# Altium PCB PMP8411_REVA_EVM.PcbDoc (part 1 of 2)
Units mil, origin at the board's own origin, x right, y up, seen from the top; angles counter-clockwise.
Board outline 4000 x 4000 mil, 6 copper layers (Top Layer, Mid-Layer 1, Mid-Layer 2, Mid-Layer 3, Mid-Layer 4, Bottom Layer), stack 118 mil thick; 118 components, 65 nets, 370 pads, 398 vias.
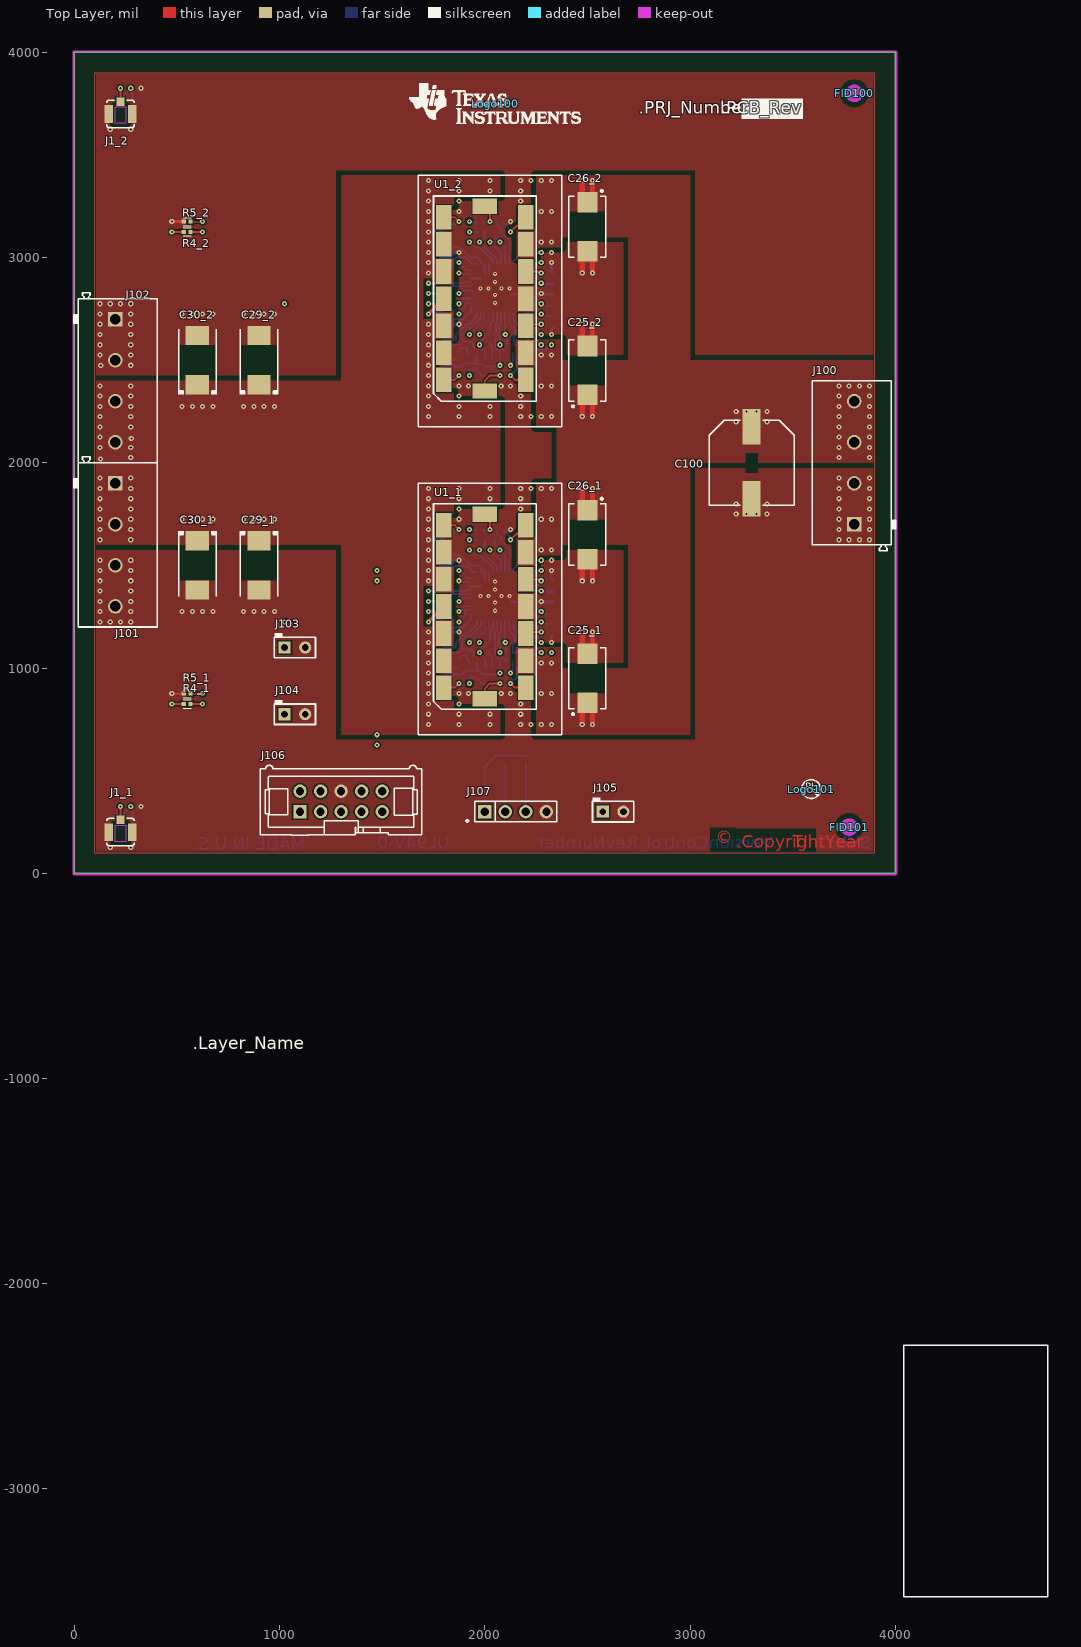
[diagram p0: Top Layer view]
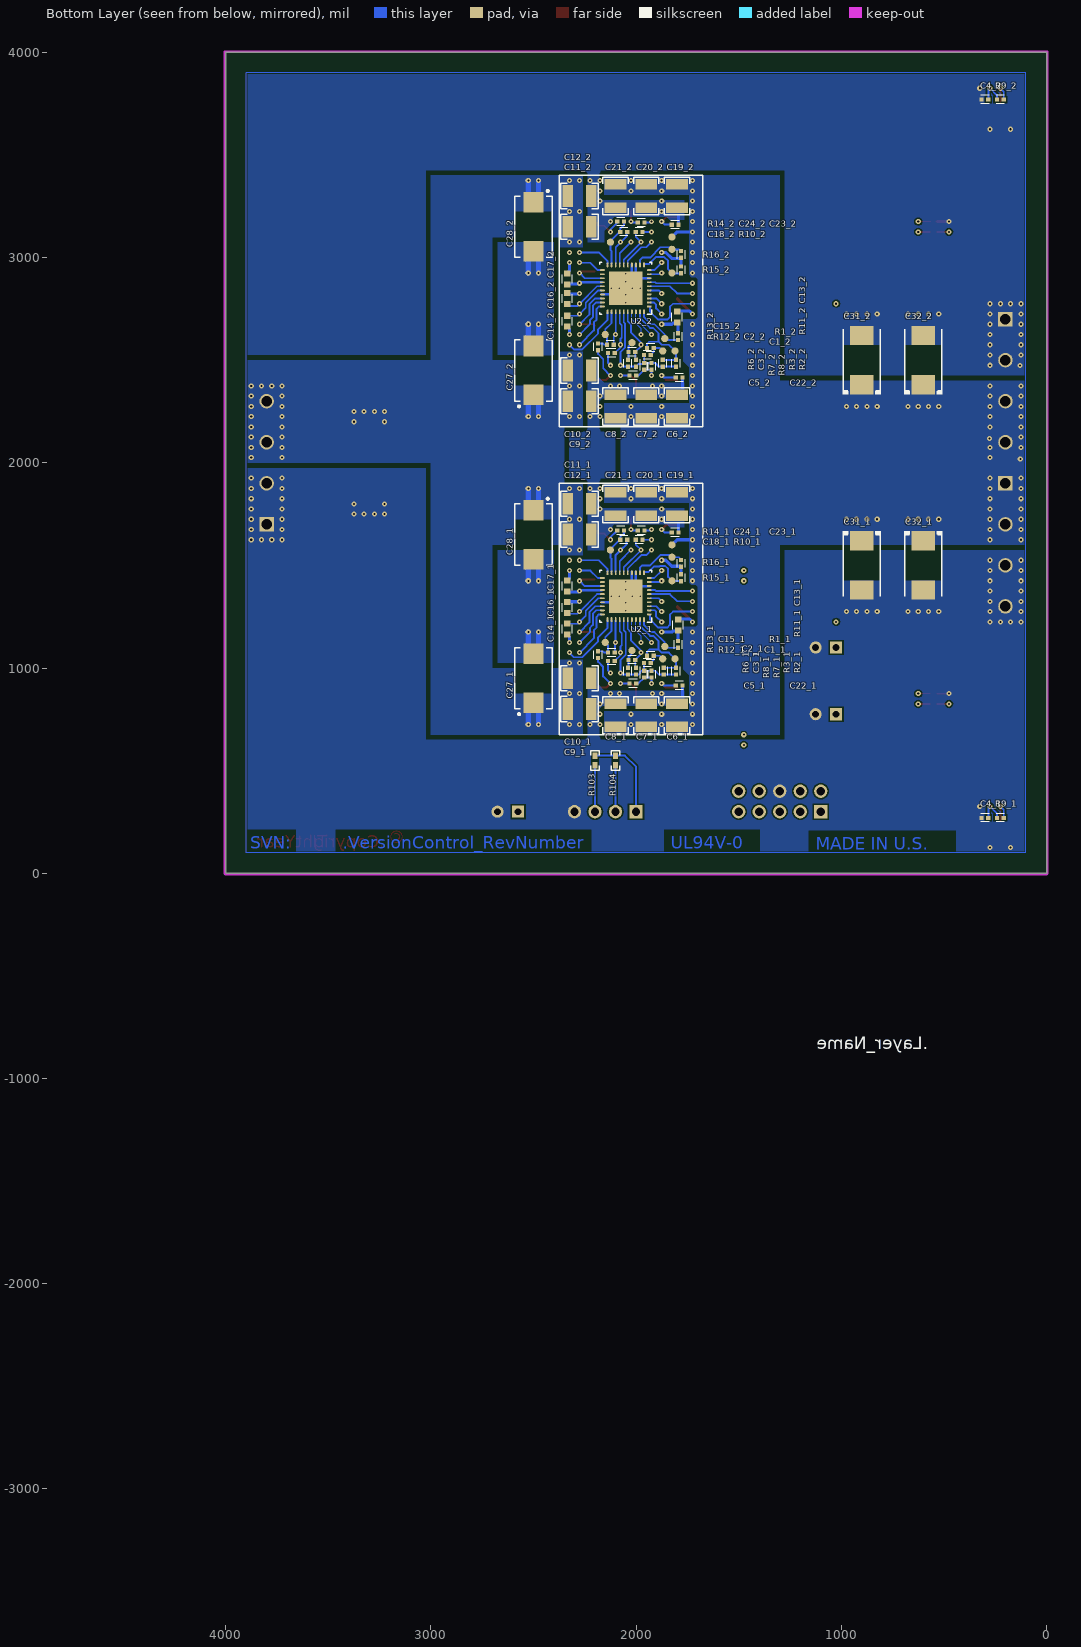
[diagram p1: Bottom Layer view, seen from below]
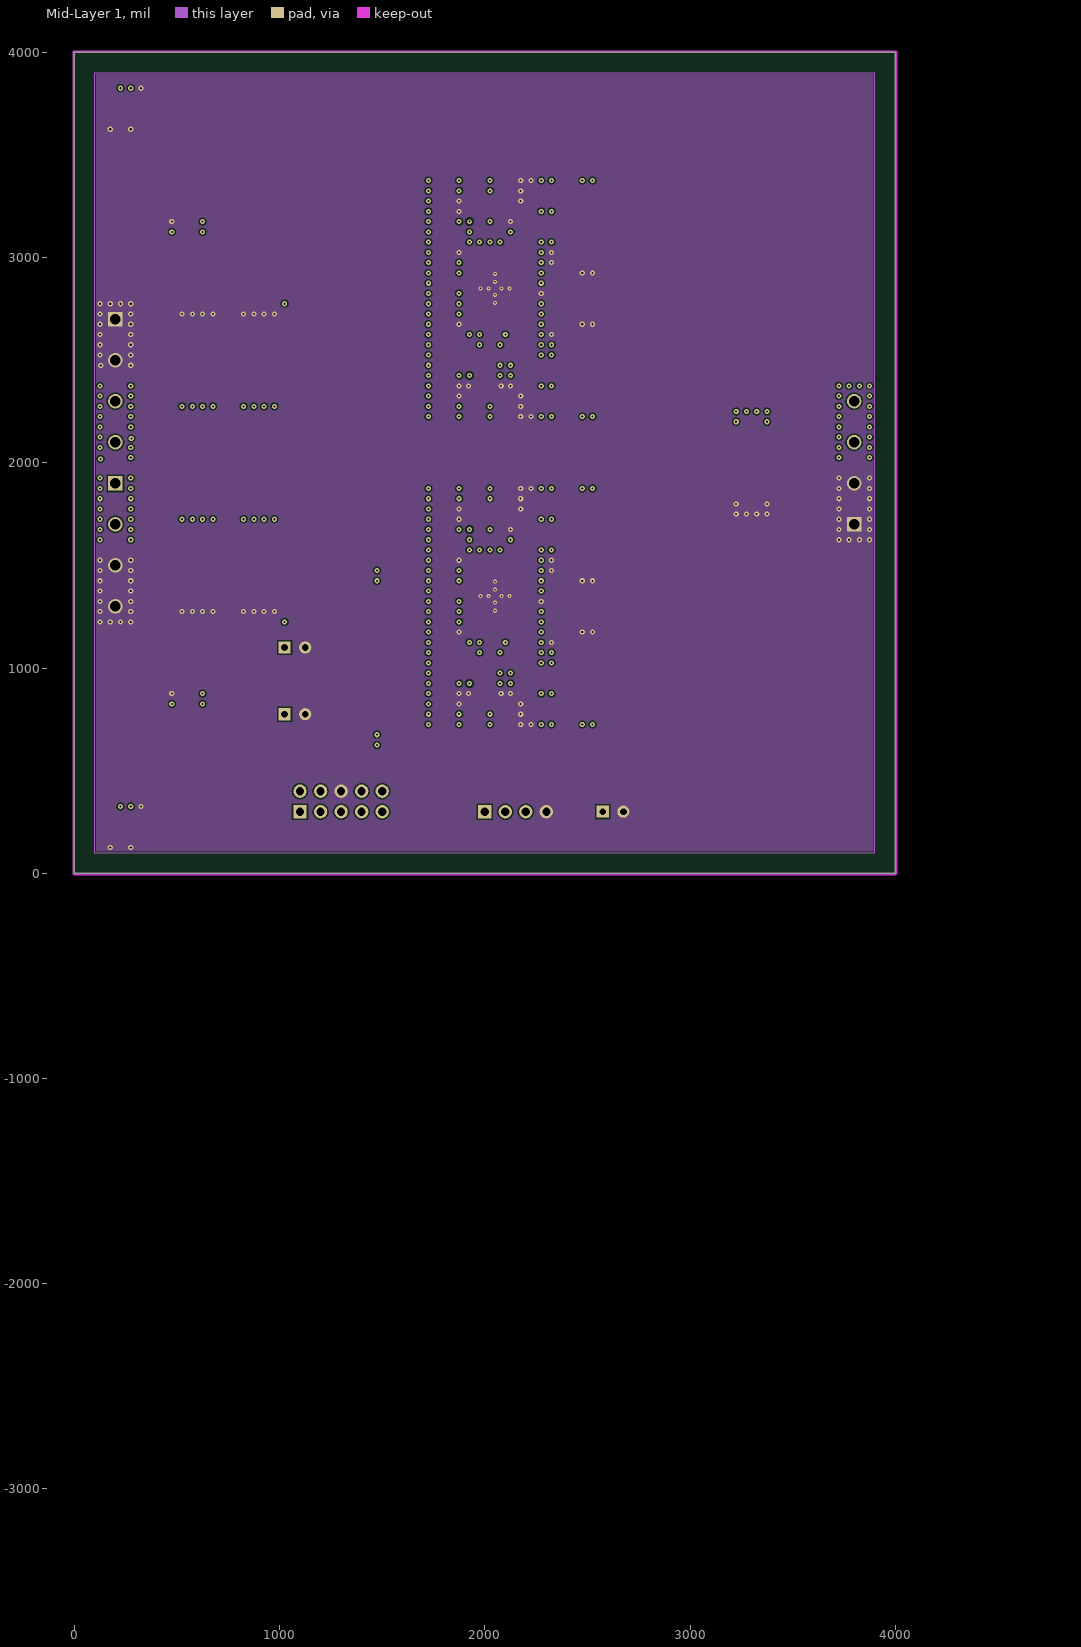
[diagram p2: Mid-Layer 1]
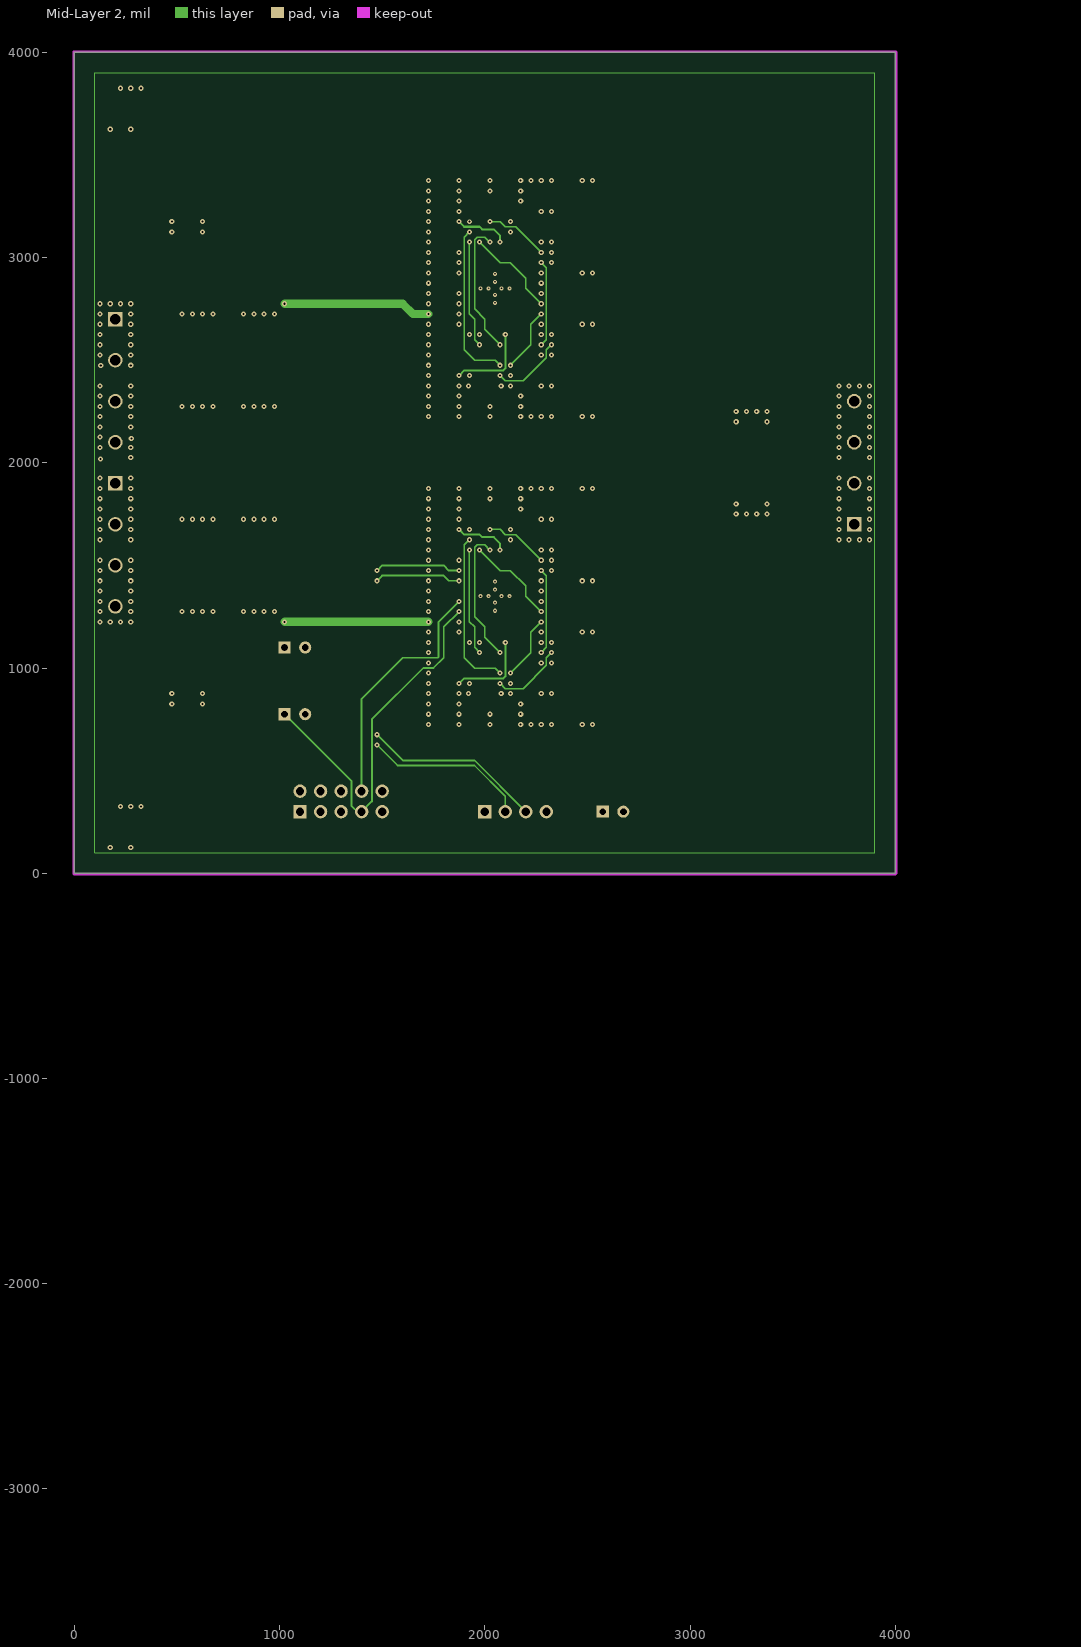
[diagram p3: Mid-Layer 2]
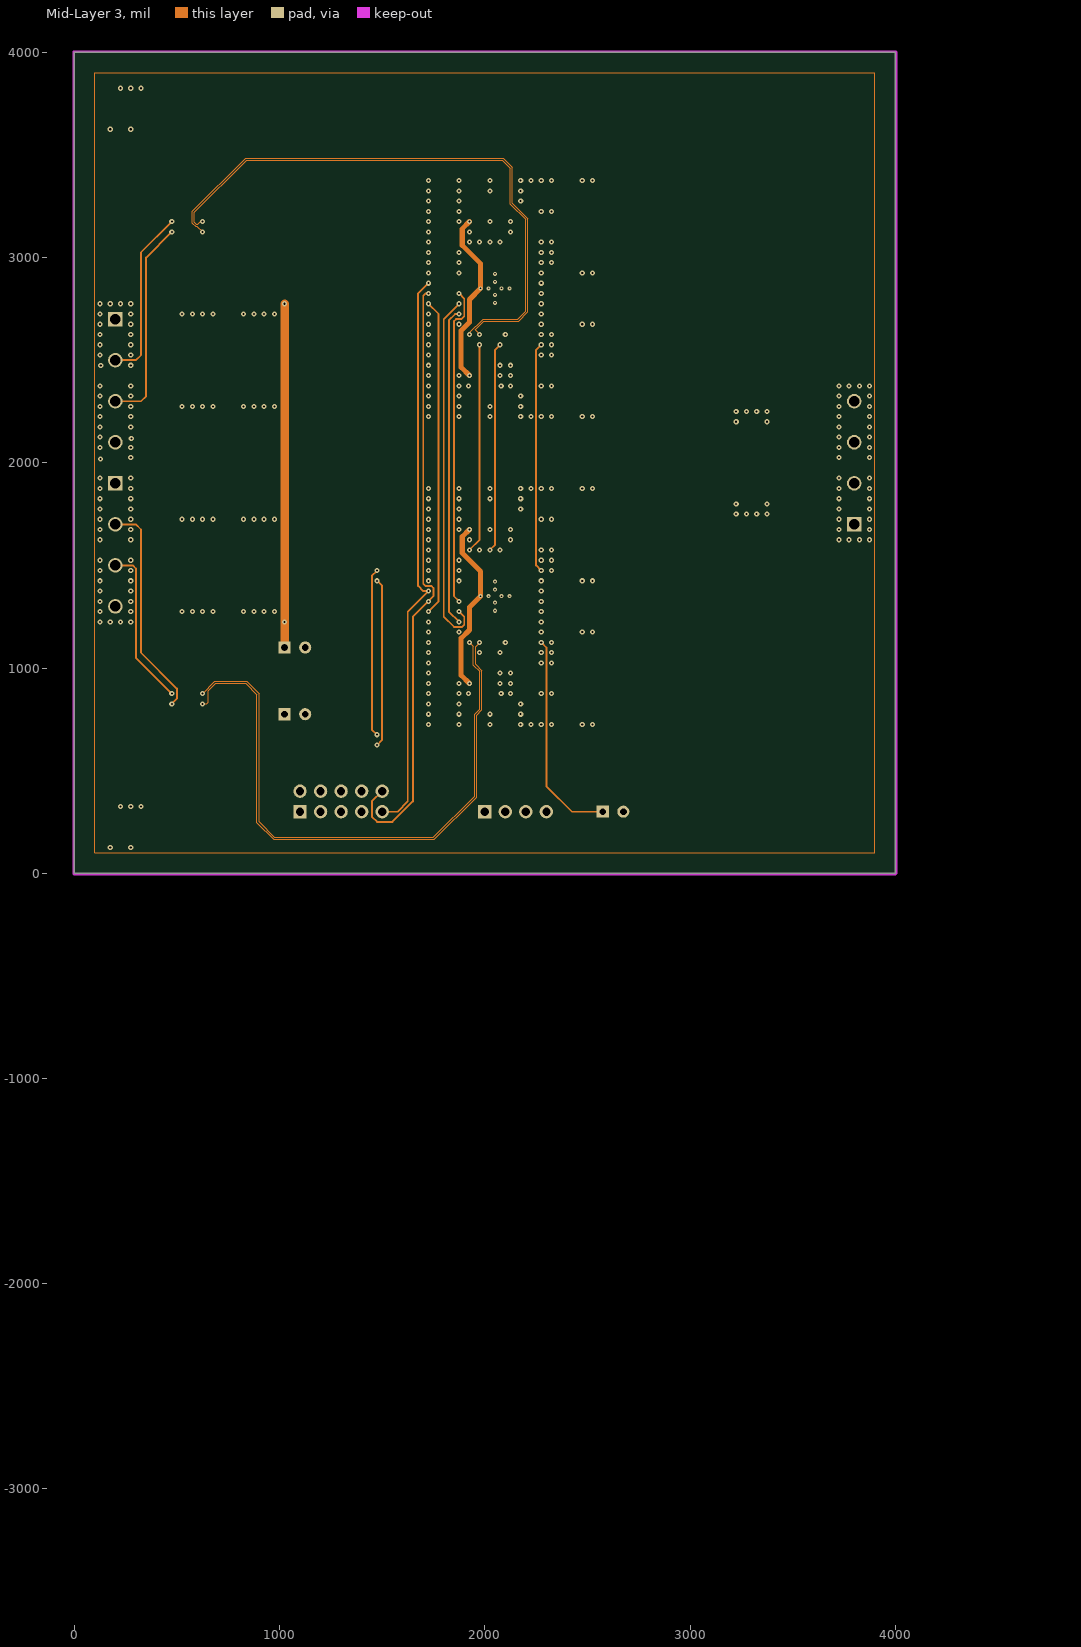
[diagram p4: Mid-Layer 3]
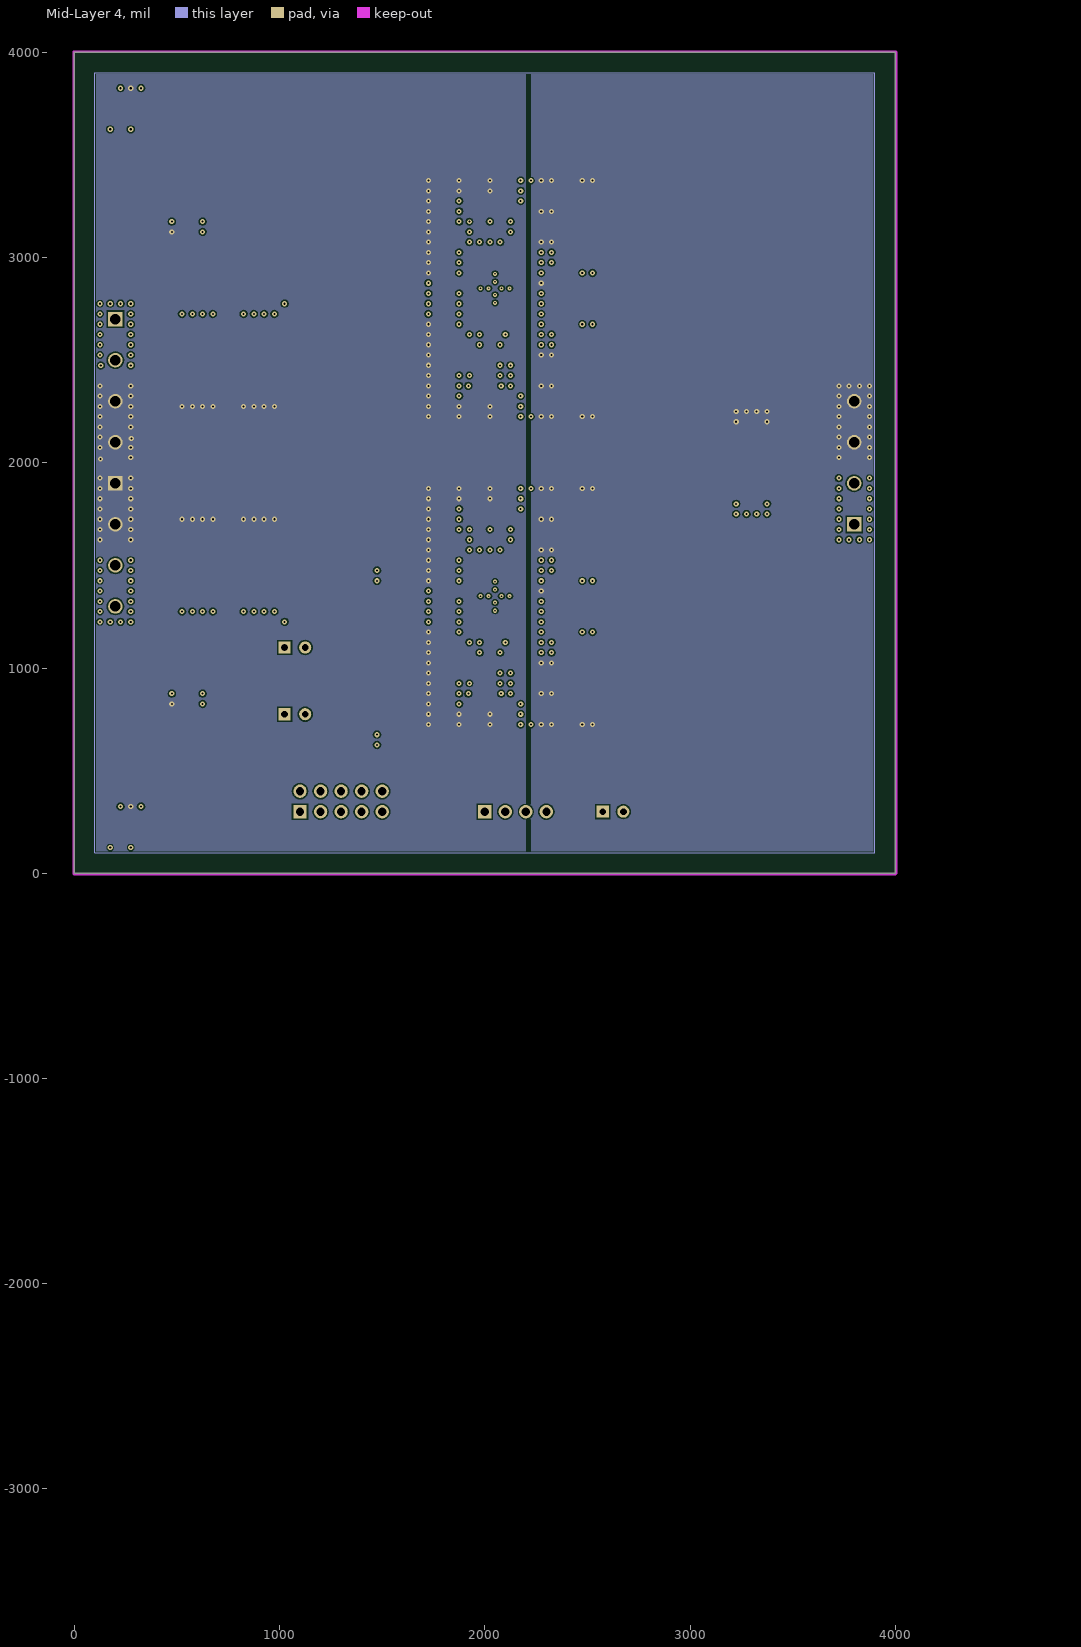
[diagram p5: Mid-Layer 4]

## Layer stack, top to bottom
Top Solder: solder mask 0.4, Solder Resist, Dk 3.5
Top Layer: signal copper 1.4
Dielectric1: core 59.2, FR-4, Dk 4.8
Mid-Layer 1: signal copper 1.4
Dielectric5: dielectric 12.6, FR-4, Dk 4.8
Mid-Layer 2: signal copper 1.4
Dielectric2: dielectric 12.6, FR-4, Dk 4.8
Mid-Layer 3: signal copper 1.4
Dielectric3: dielectric 12.6, FR-4, Dk 4.8
Mid-Layer 4: signal copper 1.4
Dielectric4: dielectric 12.6, FR-4, Dk 4.8
Bottom Layer: signal copper 1.4
Bottom Solder: solder mask 0.4, Solder Resist, Dk 3.5

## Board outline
0,0 4000,0 4000,4000 0,4000

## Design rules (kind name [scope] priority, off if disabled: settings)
AcuteAngle [All] p1 off: minimum=4.50000000000000E+0001 checktracksonly=FALSE
AssemblyTestPointUsage [All] p1: valid=2
AssemblyTestpoint [All] p1: testpointundercomponent=TRUE minsize=30 maxsize=100 preferedsize=35 minholesize=0 maxholesize=40 preferedholesize=10 testpointgrid=1 usegrid=TRUE gridtolerance=0.01 allowsidetop=TRUE allowsidebottom=TRUE
Clearance Clearance_Keepouts [((IsTrack Or IsArc) And Not InPoly) And IsFree and IsKeepOut vs ((IsTrack Or IsArc) And Not InPoly) And IsFree and IsKeepOut] p1: gap=0
Clearance Clearance_BoardEdge_MountingHoles [OnCopper and InComponentClass('Mounting Holes') vs IsKeepOut] p2: gap=40
Clearance Clearance_BoardEdge_Poly [OnCopper and InPoly vs IsKeepOut] p3: gap=25
Clearance Clearance_BoardEdge [OnCopper and Not InComponentClass('Logo') and not InComponentClass('FiducialMark') and not InRegion(1000,500,4000,800) and Not IsKeepout vs IsKeepOut] p4: gap=5
Clearance Clearance_Poly [InPolygon] p5: gap=7 except(25: Fill-Fill SMDPad-Text Fill-Text Poly-Poly Fill-Region Poly-Region Region-Region Fill-Poly Via-Text Poly-Text Track-Text Text-Text Arc-Text Region-Text THPad-Text)
Clearance [All] p6: gap=5 except(7.87: Fill-Fill SMDPad-Text Fill-Text Poly-Poly Fill-Region Arc-Region SMDPad-Region Poly-Region THPad-Region Region-Region Fill-Poly Via-Text Poly-Text Via-Region Track-Text Text-Text Arc-Text Track-Region Region-Text THPad-Text)
ComponentClearance ComponentClearance_MountingHoles_FiducialMarks [InComponentClass('Mounting Holes') vs InComponentClass('FiducialMark')] p1 off: gap=50 collisioncheckmode=3 verticalgap=10 showdistances=FALSE
ComponentClearance ComponentClearance_Shunt [InComponentClass('Header') vs InComponentClass('Shunt')] p2 off: gap=0 collisioncheckmode=3 verticalgap=0 showdistances=FALSE
ComponentClearance ComponentClearance_Logo [InComponentClass('Logo')] p3 off: gap=50 collisioncheckmode=3 verticalgap=10 showdistances=FALSE
ComponentClearance ComponentClearance_ScrewToNut [(HasFootprint('NY PMS 440 0025 PH')) vs (HasFootprint('Keystone_1902C'))] p4 off: gap=5 collisioncheckmode=3 verticalgap=10 showdistances=FALSE
ComponentClearance ComponentClearance_MountingHoles [InComponentClass('Mounting Holes')] p5 off: gap=250 collisioncheckmode=3 verticalgap=100000 showdistances=FALSE
ComponentClearance ComponentClearance_SmallPassives [HasFootprint('0201*') or HasFootprint('0402*') or HasFootprint('0508') or HasFootprint('0603*') or HasFootprint('0612') or HasFootprint('0805*') or HasFootprint('0815*') or HasFootprint('0830*') or HasFootprint('1206*') or HasFootprint('1210*') or HasFootprint('1808*') or HasFootprint('1812*') or HasFootprint('1825*') or HasFootprint('2010*') or HasFootprint('2220*') or HasFootprint('2225*') or HasFootprint('2512*') or HasFootprint('2728*') or HasFootprint('3518*') vs HasFootprint('0201*') or HasFootprint('0402*') or HasFootprint('0508') or HasFootprint('0603*') or HasFootprint('0612') or HasFootprint('0805*') or HasFootprint('0815*') or HasFootprint('0830*') or HasFootprint('1206*') or HasFootprint('1210*') or HasFootprint('1808*') or HasFootprint('1812*') or HasFootprint('1825*') or HasFootprint('2010*') or HasFootprint('2220*') or HasFootprint('2225*') or HasFootprint('2512*') or HasFootprint('2728*') or HasFootprint('3518*')] p6 off: gap=20 collisioncheckmode=3 verticalgap=10 showdistances=FALSE
ComponentClearance ComponentClearance_THtoSMT [IsThruComponent vs IsSMTComponent] p7 off: gap=100 collisioncheckmode=3 verticalgap=30 showdistances=FALSE
ComponentClearance ComponentClearance_THtoTH [IsThruComponent vs IsThruComponent] p8 off: gap=118.11 collisioncheckmode=3 verticalgap=30 showdistances=FALSE
ComponentClearance [All] p9 off: gap=40 collisioncheckmode=3 verticalgap=10 showdistances=FALSE
DiffPairsRouting [All] p1: maxlimit=100 minlimit=10 mostfreqgap=10 toplayer_minwidth=15 toplayer_maxwidth=15 toplayer_prefwidth=15 midlayer1_minwidth=15 midlayer1_maxwidth=15 midlayer1_prefwidth=15 midlayer2_minwidth=15 midlayer2_maxwidth=15 midlayer2_prefwidth=15 midlayer3_minwidth=15 midlayer3_maxwidth=15 midlayer3_prefwidth=15 midlayer4_minwidth=15 midlayer4_maxwidth=15 midlayer4_prefwidth=15 bottomlayer_minwidth=15 bottomlayer_maxwidth=15 bottomlayer_prefwidth=15 maxuncoupledlength=1000
FabricationTestPointUsage TestPointUsage [All] p1: valid=2 allowmultiple=FALSE
FabricationTestpoint Testpoint [All] p1: side=3 testpointundercomponent=TRUE minsize=30 maxsize=100 preferedsize=35 minholesize=0 maxholesize=40 preferedholesize=10 testpointgrid=1 allowsidetop=TRUE allowsidebottom=TRUE usegrid=TRUE gridtolerance=0.01
FanoutControl Fanout_LCC [IsLCC] p1: bgadir=Out bgaviamode=Centered fanoutstyle=Auto fanoutdirection=Alternating viagrid=1 // Fanout_LCC (Default Rule)
FanoutControl Fanout_BGA [IsBGA] p2: bgadir=Out bgaviamode=Centered fanoutstyle=Auto fanoutdirection=Alternating viagrid=1 // Fanout_BGA (Default Rule)
FanoutControl Fanout_Default [All] p4: bgadir=Out bgaviamode=Centered fanoutstyle=Auto fanoutdirection=Alternating viagrid=1 // Fanout_Default (Default Rule)
FanoutControl Fanout_Small [(CompPinCount < 5)] p5: bgadir=Out bgaviamode=Centered fanoutstyle=Auto fanoutdirection=OutThenIn viagrid=1 // Fanout_Small (Default Rule)
Height [All] p1 off: minheight=0 maxheight=1000 prefheight=500
HoleSize [All] p1 off: absolutevalues=TRUE maxlimit=251 minlimit=7 maxpercent=80.000 minpercent=20.000
HoleToHoleClearance [All] p1 off: gap=10 allowstackedmicrovias=TRUE
LayerPairs [All] p1 off: enforce=TRUE
MinimumAnnularRing MinimumAnnularRing_ThermalPadVias [IsVia and InAnyComponent] p1 off: minimumring=5.91
MinimumAnnularRing [All] p2 off: minimumring=9
MinimumSolderMaskSliver MinimumSolderMaskSliver_Logo [InComponentClass('Logo') vs InComponentClass('Logo')] p1 off: minsoldermaskwidth=0.7
MinimumSolderMaskSliver [All] p2 off: minsoldermaskwidth=3.94
NetAntennae [All] p1 off: netantennaetolerance=0
PlaneClearance [All] p1: clearance=8
PlaneConnect NO_SHAPE_CONNECT_VIA [(ObjectKind = 'Via') And (ViaDiameter = '23')] p1: planeconnectstyle=NoConnect reliefexpansion=10 reliefentries=4 reliefconductorwidth=10 reliefairgap=10
PlaneConnect PlaneConnect_1 [All] p2: planeconnectstyle=Direct reliefexpansion=20 reliefentries=4 reliefconductorwidth=10 reliefairgap=10
PolygonConnect NOSHAPECONNECT_VIA [(ObjectKind = 'Via') And (ViaDiameter = '23')] p1: connectstyle=NoConnect reliefconductorwidth=10 reliefentries=4 polygonreliefangle="90 Angle" airgapwidth=10
PolygonConnect [All] p2: connectstyle=Direct reliefconductorwidth=10 reliefentries=4 polygonreliefangle="90 Angle" airgapwidth=10
RoutingLayers [All] p1: top layer_v5=TRUE mid layer 1_v5=FALSE mid layer 2_v5=TRUE mid layer 3_v5=TRUE mid layer 4_v5=FALSE bottom layer_v5=TRUE
RoutingVias ThermalPadVias [IsVia and InAnyComponent] p1: holewidth=10 width=25 viastyle="Through Hole" minholewidth=7 minwidth=15 maxholewidth=15 maxwidth=30
RoutingVias [All] p2: holewidth=10 width=25 viastyle="Through Hole" minholewidth=7 minwidth=15 maxholewidth=40 maxwidth=65
SilkToBoardRegionClearance [Not ((IsComment or IsDesignator) And (Hide <> 'False')) and not InRegion(1000,500,4000,800)] p1 off:
SilkToSilkClearance SilkToSilkClearance_Pb-FreeLogo [(HasFootprint('Pb-Free_Overlay_Medium') OR HasFootprint('Pb-Free_Overlay_Small')) vs (HasFootprint('Pb-Free_Overlay_Medium') OR HasFootprint('Pb-Free_Overlay_Small'))] p1 off: silktosilkclearance=0
SilkToSilkClearance [All] p2 off: silktosilkclearance=5
SilkToSolderMaskClearance "Silk to Solder Mask Opening" [All] p1 off: minsilkscreentomaskgap=1 clearancetoexposedcopper=FALSE
SolderMaskExpansion [All] p1: expansion=1.97
UnpouredPolygon [All] p1: allowunpoured=FALSE
Width [All] p1: maxlimit=100 minlimit=4 preferedwidth=9 checkconnectedcopper=TRUE
7 further rules are at their usual default settings.

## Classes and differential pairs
component class AssemblyNote: ZZ100
component class FiducialMark: FID100 FID101
component class PMP8411-P3: C100 FID100 FID101 J100 J101 J102 J103 J104 J105 J106 J107 Logo100 Logo101 R103 R104 ZZ100
component class Logo: Logo100
component class Header: J103 J104 J105 J107
component class PMP8411-P1: C1_1 C2_1 C3_1 C4_1 C5_1 C6_1 C7_1 C8_1 C9_1 C10_1 C11_1 C12_1 C13_1 C14_1 C15_1 C16_1 C17_1 C18_1 C19_1 C20_1 C21_1 C22_1 C23_1 C24_1 C25_1 C26_1 C27_1 C28_1 C29_1 C30_1 C31_1 C32_1 J1_1 R1_1 R2_1 R3_1 R4_1 R5_1 R6_1 R7_1 R8_1 R9_1 R10_1 R11_1 R12_1 R13_1 R14_1 R15_1 R16_1 U1_1 U2_1
component class PMP8411-P2: C1_2 C2_2 C3_2 C4_2 C5_2 C6_2 C7_2 C8_2 C9_2 C10_2 C11_2 C12_2 C13_2 C14_2 C15_2 C16_2 C17_2 C18_2 C19_2 C20_2 C21_2 C22_2 C23_2 C24_2 C25_2 C26_2 C27_2 C28_2 C29_2 C30_2 C31_2 C32_2 J1_2 R1_2 R2_2 R3_2 R4_2 R5_2 R6_2 R7_2 R8_2 R9_2 R10_2 R11_2 R12_2 R13_2 R14_2 R15_2 R16_2 U1_2 U2_2

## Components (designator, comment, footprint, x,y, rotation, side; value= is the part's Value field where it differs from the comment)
C1_1 "C1005C0G1E102J" 0402S 1945,1025 r0 bottom
C1_2 "C1005C0G1E102J" 0402S 1945,2525 r0 bottom
C2_1 "C1005C0G1E102J" 0402S 2020,1040 r0 bottom
C2_2 "C1005C0G1E102J" 0402S 2020,2540 r0 bottom
C3_1 "C1005C0G1H471J" 0402S 2000,985 r270 bottom
C3_2 "C1005C0G1H471J" 0402S 2000,2485 r270 bottom
C4_1 "C1005X7R1H104K" 0402S 300,270 r0 bottom
C4_2 "C1005X7R1H104K" 0402S 300,3770 r0 bottom
C5_1 "C1005C0G1E102J" 0402S 2015,925 r0 bottom
C5_2 "C1005C0G1E102J" 0402S 2015,2425 r0 bottom
C6_1 "GRM32EC80J107ME20L" 1210 1800,770 r90 bottom
C6_2 "GRM32EC80J107ME20L" 1210 1800,2275 r90 bottom
C7_1 "GRM32EC80J107ME20L" 1210 1950,770 r90 bottom
C7_2 "GRM32EC80J107ME20L" 1210 1950,2275 r90 bottom
C8_1 "GRM32EC80J107ME20L" 1210 2100,770 r90 bottom
C8_2 "GRM32EC80J107ME20L" 1210 2100,2275 r90 bottom
C9_1 "GRM32ER61C226KE20L" 1210 2275,800 r180 bottom
C9_2 "GRM32ER61C226KE20L" 1210 2275,2300 r180 bottom
C10_1 "GRM32ER61C226KE20L" 1210 2275,950 r180 bottom
C10_2 "GRM32ER61C226KE20L" 1210 2275,2450 r180 bottom
C11_1 "GRM32ER61C226KE20L" 1210 2275,1800 r180 bottom
C11_2 "GRM32ER61C226KE20L" 1210 2275,3150 r180 bottom
C12_1 "GRM32ER61C226KE20L" 1210 2275,1650 r180 bottom
C12_2 "GRM32ER61C226KE20L" 1210 2275,3300 r180 bottom
C13_1 "GRM188R61C225KAAD" 0603S 1795,1210 r270 bottom
C13_2 "GRM188R61C225KAAD" 0603S 1800,2710 r270 bottom
C14_1 "C1608X5R1E105K080AC" 0603S 2335,1190 r270 bottom
C14_2 "C1608X5R1E105K080AC" 0603S 2335,2690 r270 bottom
C15_1 "C1005X7R1C224K050BC" 0402S 2120,1075 r180 bottom
C15_2 "C1005X7R1C224K050BC" 0402S 2125,2575 r180 bottom
C16_1 "C1608X5R1E105K080AC" 0603S 2335,1295 r90 bottom
C16_2 "C1608X5R1E105K080AC" 0603S 2335,2800 r90 bottom
C17_1 "C1608X5R1E105K080AC" 0603S 2335,1400 r90 bottom
C17_2 "C1608X5R1E105K080AC" 0603S 2335,2895 r90 bottom
C18_1 "C1005X7R1C224K050BC" 0402S 2060,1625 r180 bottom
C18_2 "C1005X7R1C224K050BC" 0402S 2060,3125 r180 bottom
C19_1 "GRM32EC80J107ME20L" 1210 1800,1800 r270 bottom
C19_2 "GRM32EC80J107ME20L" 1210 1800,3300 r270 bottom
C20_1 "GRM32EC80J107ME20L" 1210 1950,1800 r270 bottom
C20_2 "GRM32EC80J107ME20L" 1210 1950,3300 r270 bottom
C21_1 "GRM32EC80J107ME20L" 1210 2100,1800 r270 bottom
C21_2 "GRM32EC80J107ME20L" 1210 2100,3300 r270 bottom
C22_1 "C1005X5R0J105M" 0402S 1790,915 r180 bottom
C22_2 "C1005X5R0J105M" 0402S 1790,2415 r180 bottom
C23_1 "C1005X5R0J105M" 0402S 1810,1660 r180 bottom
C23_2 "C1005X5R0J105M" 0402S 1810,3160 r180 bottom
C24_1 "C1005C0G1E102J" 0402S 1975,1670 r180 bottom
C24_2 "C1005C0G1E102J" 0402S 1975,3170 r180 bottom
C25_1 "TPSD476M016R0080" 7343-31 2500,950 r90 top
C25_2 "TPSD476M016R0080" 7343-31 2500,2450 r90 top
C26_1 "TPSD476M016R0080" 7343-31 2500,1650 r270 top
C26_2 "TPSD476M016R0080" 7343-31 2500,3150 r270 top
C27_1 "TPSD476M016R0080" 7343-31 2500,950 r90 bottom
C27_2 "TPSD476M016R0080" 7343-31 2500,2450 r90 bottom
C28_1 "TPSD476M016R0080" 7343-31 2500,1650 r270 bottom
C28_2 "TPSD476M016R0080" 7343-31 2500,3150 r270 bottom
C29_1 "4TPE470MAL" CAPSMT_6_D3L 900,1500 r270 top
C29_2 "4TPE470MAL" CAPSMT_6_D3L 900,2500 r90 top
C30_1 "4TPE470MAL" CAPSMT_6_D3L 600,1500 r270 top
C30_2 "4TPE470MAL" CAPSMT_6_D3L 600,2500 r90 top
C31_1 "4TPE470MAL" CAPSMT_6_D3L 900,1500 r270 bottom
C31_2 "4TPE470MAL" CAPSMT_6_D3L 900,2500 r90 bottom
C32_1 "4TPE470MAL" CAPSMT_6_D3L 600,1500 r270 bottom
C32_2 "4TPE470MAL" CAPSMT_6_D3L 600,2500 r90 bottom
C100 "16SVPE470M" CAPSMT_62_JC0 3300,2000 r270 top
FID100 "Fiducial" Fiducial10-20 3800,3800 r0 top
FID101 "Fiducial" Fiducial10-20 3775,225 r0 top
J1_1 "U.FL-R-SMT-1" CONN_UFL-R-SMT-1 225,200 r270 top
J1_2 "U.FL-R-SMT-1" CONN_UFL-R-SMT-1 225,3700 r270 top
J100 "1715747" Phoenix_1715747 3800,2000 r90 top
J101 "1715747" Phoenix_1715747 200,1600 r270 top
J102 "1715747" Phoenix_1715747 200,2400 r270 top
J103 "800-10-002-10-001000" Mill-Max_800-10-002-10-001000 1075,1100 r0 top
J104 "800-10-002-10-001000" Mill-Max_800-10-002-10-001000 1075,775 r0 top
J105 "800-10-002-10-001000" Mill-Max_800-10-002-10-001000 2625,300 r0 top
J106 "N2510-6002-RB" CONN_2510-6002 1300,350 r0 top
J107 "TSW-104-07-G-S" TSW-104-07-G-S 2150,300 r0 top
Logo100 "Texas Instruments" TI_Stacked_Overlay_Small 2050,3750 r0 top
Logo101 "Pb-Free Symbol" Pb-Free_Overlay_Small 3590,410 r0 top
R1_1 "CRCW0402511RFKED" 0402S 1930,1060 r180 bottom
R1_2 "CRCW0402511RFKED" 0402S 1930,2560 r180 bottom
R2_1 "PCF0402-12-10KBT1" 0402S 1805,985 r90 bottom
R2_2 "PCF0402-12-10KBT1" 0402S 1805,2485 r90 bottom
R3_1 "CRCW0402100KFKED" 0402S 1865,985 r90 bottom
R3_2 "CRCW0402100KFKED" 0402S 1870,2485 r90 bottom
R4_1 "CRCW040210R0FKED" 0402S 550,825 r0 top
R4_2 "CRCW040210R0FKED" 0402S 550,3125 r0 top
R5_1 "ERJ-2GE0R00X" 0402S 550,875 r0 top
R5_2 "ERJ-2GE0R00X" 0402S 550,3175 r0 top
R6_1 "CRCW040210K0FKED" 0402S 2040,985 r90 bottom
R6_2 "CRCW040210K0FKED" 0402S 2040,2485 r90 bottom
R7_1 "CRCW040220K0FKED" 0402S 1925,970 r90 bottom
R7_2 "CRCW040220K0FKED" 0402S 1960,2470 r90 bottom
R8_1 "CRCW0402100KFKED" 0402S 1960,970 r90 bottom
R8_2 "CRCW0402100KFKED" 0402S 1925,2470 r90 bottom
R9_1 "CRCW040249R9FKED" 0402S 225,270 r0 bottom
R9_2 "CRCW040249R9FKED" 0402S 225,3770 r0 bottom
R10_1 "ERJ-2GE0R00X" 0402S 1985,1625 r0 bottom
R10_2 "ERJ-2GE0R00X" 0402S 1985,3125 r0 bottom
R11_1 "CRCW040249K9FKED" 0402S 1795,1115 r270 bottom
R11_2 "CRCW040249K9FKED" 0402S 1795,2615 r270 bottom
R12_1 "PCF0402-12-10KBT1" 0402S 2120,1035 r0 bottom
R12_2 "PCF0402-12-10KBT1" 0402S 2120,2535 r0 bottom
R13_1 "CRCW040210R0FKED" 0402S 2185,1065 r270 bottom
R13_2 "CRCW040210R0FKED" 0402S 2185,2565 r270 bottom
R14_1 "CRCW040210R0FKED" 0402S 2075,1670 r0 bottom
R14_2 "CRCW040210R0FKED" 0402S 2075,3175 r0 bottom
R15_1 "CRCW040238K3FKED" 0402S 1780,1440 r270 bottom
R15_2 "CRCW040238K3FKED" 0402S 1780,2940 r270 bottom
R16_1 "CRCW040238K3FKED" 0402S 1780,1510 r90 bottom
R16_2 "CRCW040253K6FKED" 0402S 1780,3015 r90 bottom
R103 "RG1005P-101-B-T5" 0402 2200,550 r90 bottom
R104 "RG1005P-101-B-T5" 0402 2100,550 r90 bottom
U1_1 "OKLP-X/45-W12-C" OKLP-X_45-W12-C 2000,1300 r90 top
U1_2 "OKLP-X/45-W12-C" OKLP-X_45-W12-C 2000,2800 r90 top
U2_1 "TPS40425RHA" RHA0040B 2050,1350 r0 bottom
U2_2 "TPS40425RHA" RHA0040B 2050,2850 r0 bottom
ZZ100 "This Assembly Note is for PCB labels only" AssemblyNoteLabel 100,4400 r0 top

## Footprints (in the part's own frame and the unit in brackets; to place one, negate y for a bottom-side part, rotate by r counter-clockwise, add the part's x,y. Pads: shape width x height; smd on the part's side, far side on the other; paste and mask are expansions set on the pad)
0402 [mm] "0402 from SM-752 data"
  rect 0.8x0.6 smd: 1(-0.6,0) 2(0.6,0)
  silkscreen extent -1.22,-0.52 1.22,0.52, body extent -0.55,-0.3 0.55,0.3, height 0.6
0402S [mil] "SMALL 0402"
  rect 21x20 smd paste+0: 1(-16.5,0) 2(16.5,0)
  silkscreen extent -20,-20 20,20
0603S [mil]
  rect 30x32 smd paste+0: 1(-26.5,0) 2(26.5,0)
  silkscreen extent -20,-25 20,25
1210 [mm] "1210 from SM-752 data"
  rect 1.3x2.7 smd: 1(-1.45,0) 2(1.45,0)
  silkscreen extent -2.32,-1.57 2.32,1.57, body extent -1.7,-1.35 1.7,1.35, height 1.35
7343-31 [mm] "Medium Density based on Kemet T495 dimensions"
  rect 2.55x2.45 smd: 1(-3.025,0) 2(3.025,0)
  silkscreen extent -4.56,-2.3 3.8,2.3, body extent -3.8,-2.3 3.8,2.3, height 3.1
AssemblyNoteLabel [mil] "Assembly Note for PCB Labels"
CAPSMT_6_D3L [mm] "Panasonic recommended land pattern for size code D3L"
  rect 2.4x2.9 smd: 1(-3.05,0) 2(3.05,0)
  silkscreen extent -4.25,-2.39 3.8,2.39, body extent -3.8,-2.3 3.8,2.3, height 2.9
CAPSMT_62_JC0 [mm] "10 x 12.2mm:  Chemi-Con JC0"
  rect 4.4x2.2 smd: 1(-4.45,0) 2(4.45,0)
  silkscreen extent -5.25,-5.25 5.25,5.25, body extent -5.26,-5.26 5.26,5.26, height 12.7
CONN_2510-6002 [mm] "3M 2500 series TS-0770-L December 15, 2011"
  rect 1.65x1.65 hole 1.016 mask+0: 1(-5.08,-1.27)
  round 1.65 hole 1.016 mask+0: 2(-5.08,1.27) 3(-2.54,-1.27) 4(-2.54,1.27) 5(0,-1.27) 6(0,1.27) 7(2.54,-1.27) 8(2.54,1.27) 9(5.08,-1.27) 10(5.08,1.27)
  silkscreen extent -10.01,-4.17 10.01,4.47, body extent -10.01,-4.11 10.01,4.52, height 9.92
CONN_UFL-R-SMT-1 [mm] "Hirose recommended land pattern http://www.hirose.co.jp/cataloge_hp/e32119372.pdf 2009.2"
  rect 1.05x1 smd: 1(-1.525,0)
  rect 2.2x1.05 smd: 2(0,1.475) 3(0,-1.475)
  Top Layer keep-out region: -0.8,-0.7 1.1,-0.7 1.1,0.7 -0.8,0.7
  silkscreen extent -1.7,-1.7 1.7,1.7, body extent -1.55,-1.5 1.55,1.5, height 1.27
Fiducial10-20 [mm]
  round 1 smd mask+0.5: 1(0,0)
  Top Layer keep-out circle w1.178: c0,0 r0.5
Mill-Max_800-10-002-10-001000 [mm] "Mill-Max"
  rect 1.5x1.5 hole 0.85: 1(-1.27,0)
  round 1.5 hole 0.85: 2(1.27,0)
  silkscreen extent -2.54,-1.27 2.54,1.78, body extent -2.54,-1.27 2.54,1.27, height 8.13
OKLP-X_45-W12-C [mil] "SMD, 16-Leads, Body 25.4x12.7mm"
  rect 120x75 smd: 1(-396,200) 2(-264,200) 3(-132,200) 4(0,200) 5(132,200) 6(264,200) 7(396,200) 8(396,-200) 9(264,-200) 10(132,-200) 11(0,-200) 12(-132,-200) 13(-264,-200) 14(-396,-200)
  rect 75x120 smd: 15(-450,0) 16(450,0)
  silkscreen extent -500,-250 500,250, body extent -500,-250 500,250, height 490
Pb-Free_Overlay_Small [mil]
  silkscreen extent -46,-46 46,46
Phoenix_1715747 [mm] "Terminal Block, 5.08mm, 4x1, TH"
  rect 1.8x1.8 hole 1.3: 1(-7.62,0)
  round 1.8 hole 1.3: 2(-2.54,0) 3(2.54,0) 4(7.62,0)
  silkscreen extent -10.9,-5.25 10.16,5.2, body extent -10.9,-4.6 10.16,5.2, height 14.2
RHA0040B [mm] "QFN, 40-Leads, Body 6x6mm, Pitch 0.5mm, Thermal Pad 4.15 x 4.15mm, TI Recommended"
  oval 0.6x0.23 smd mask+0.07: 1(-2.9,2.25) 2(-2.9,1.75) 3(-2.9,1.25) 4(-2.9,0.75) 5(-2.9,0.25) 6(-2.9,-0.25) 7(-2.9,-0.75) 8(-2.9,-1.25) 9(-2.9,-1.75) 10(-2.9,-2.25) 21(2.9,-2.25) 22(2.9,-1.75) 23(2.9,-1.25) 24(2.9,-0.75) 25(2.9,-0.25) 26(2.9,0.25) 27(2.9,0.75) 28(2.9,1.25) 29(2.9,1.75) 30(2.9,2.25)
  oval 0.23x0.6 smd mask+0.07: 11(-2.25,-2.9) 12(-1.75,-2.9) 13(-1.25,-2.9) 14(-0.75,-2.9) 15(-0.25,-2.9) 16(0.25,-2.9) 17(0.75,-2.9) 18(1.25,-2.9) 19(1.75,-2.9) 20(2.25,-2.9) 31(2.25,2.9) 32(1.75,2.9) 33(1.25,2.9) 34(0.75,2.9) 35(0.25,2.9) 36(-0.25,2.9) 37(-0.75,2.9) 38(-1.25,2.9) 39(-1.75,2.9) 40(-2.25,2.9)
  rect 4.15x4.15 smd paste-2.1 mask+0.07: 41(0,0)
  silkscreen extent -3.22,-3.22 3.22,3.22, body extent -3.08,-3.08 3.08,3.08, height 1.01
TI_Stacked_Overlay_Small [mil]
  silkscreen extent -418,-98 418,98
TSW-104-07-G-S [mm] "Samtec 100mil, 1x4, 230 mil above insulator"
  rect 1.65x1.65 hole 1.016 mask+0: 1(-3.81,0)
  round 1.65 hole 1.016 mask+0: 2(-1.27,0) 3(1.27,0) 4(3.81,0)
  silkscreen extent -6.1,-1.27 5.08,1.27, body extent -5.08,-1.27 5.08,1.27, height 8.38

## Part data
C1_1 C1_2 C2_1 C2_2 C5_1 C5_2 C24_1 C24_2: "CAP, CERM, 1000 pF, 25 V, +/- 5%, C0G/NP0, 0402"
C3_1 C3_2: "CAP, CERM, 470 pF, 50 V, +/- 5%, C0G/NP0, 0402"
C4_1 C4_2: "CAP, CERM, 0.1 µF, 50 V, +/- 10%, C0G/NP0, 0402"
C6_1 C6_2 C7_1 C7_2 C8_1 C8_2 C19_1 C19_2 C20_1 C20_2 C21_1 C21_2: "CAP, CERM, 100 µF, 6.3 V, +/- 20%, X6S, 1210"
C9_1 C9_2 C10_1 C10_2 C11_1 C11_2 C12_1 C12_2: "CAP, CERM, 22 µF, 16 V, +/- 10%, X5R, 1210"
C13_1 C13_2: "CAP, CERM, 2.2 µF, 16 V, +/- 10%, X5R, 0603"
C14_1 C14_2 C16_1 C16_2 C17_1 C17_2: "CAP, CERM, 1 µF, 25 V, +/- 10%, X5R, 0603"
C15_1 C15_2 C18_1 C18_2: "CAP, CERM, 0.22 µF, 16 V, +/- 10%, X7R, 0402"
C22_1 C22_2 C23_1 C23_2: "CAP, CERM, 1 µF, 6.3 V, +/- 20%, X5R, 0402"
C25_1 C25_2 C26_1 C26_2 C27_1 C27_2 C28_1 C28_2: "CAP, TA, 47 µF, 16 V, +/- 20%, 0.08 ohm, SMD"
C29_1 C29_2 C30_1 C30_2 C31_1 C31_2 C32_1 C32_2: "CAP, TA, 470 µF, 4 V, +/- 20%, 0.01 ohm, SMD"
C100: "CAP, AL, 470 µF, 16 V, +/- 20%, 0.01 ohm, SMD"
FID100 FID101: "Fiducial mark.  There is nothing to buy or mount."
J1_1 J1_2: "Connector, Ultra-Mini Coaxial, SMD"
J100 J101 J102: "Terminal Block, 5.08mm, 4x1, TH"
J103 J104 J105: "Header, 100mil, 2x1, TH"
J106: "Header (shrouded), 100mil, 5x2, High-Temperature, Gold, TH"
J107: "Header, 100mil, 4x1, Gold, TH"
Logo100: library part TI_Logo, "Texas Instrument Corporate Signature"
Logo101: library part Pb-Free
R1_1 R1_2: "RES, 511, 1%, 0.063 W, 0402"
R2_1 R2_2 R12_1 R12_2: "RES, 10.0 k, 0.1%, 0.063 W, 0402"
R3_1 R3_2 R8_1 R8_2: "RES, 100 k, 1%, 0.063 W, 0402"
R4_1 R4_2 R13_1 R13_2 R14_1 R14_2: "RES, 10.0, 1%, 0.063 W, 0402"
R5_1 R5_2 R10_1 R10_2: "RES, 0, 5%, 0.063 W, 0402"
R6_1 R6_2: "RES, 10.0 k, 1%, 0.063 W, 0402"
R7_1 R7_2: "RES, 20.0 k, 1%, 0.063 W, 0402"
R9_1 R9_2: "RES, 49.9, 1%, 0.063 W, 0402"
R11_1 R11_2: "RES, 49.9 k, 1%, 0.063 W, 0402"
R15_1 R15_2 R16_1: "RES, 38.3 k, 1%, 0.063 W, 0402"
R16_2: "RES, 53.6 k, 1%, 0.063 W, 0402"
R103 R104: "RES, 100, 0.1%, 0.063 W, 0402"
U1_1 U1_2: "45A Power Block Non-Isolated DC/DC Converter, SMD, Body 25.4 x 12.7 mm"
U2_1 U2_2: "Dual output, 2-Phase, Stackable PMBUS Synchronous Buck Driverless Controller with AVS Bus, RHA0040B"
ZZ100: library part AssemblyNoteLabel

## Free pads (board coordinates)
  round 35 smd far side: 0(1810,1045) 0(1810,2545) 0(1825,1425) 0(1825,1540) 0(1825,1600) 0(1825,2925) 0(1825,3040) 0(1825,3100) 0(1860,1105) 0(1860,2605) 0(1870,1045) 0(1870,2545) 0(2020,1085) 0(2020,2585) 0(2125,1575) 0(2125,3075) 0(2150,1125) 0(2150,2625)

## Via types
v1: diameter 25, hole 10, Top Layer to Bottom Layer, 378 vias
v2: diameter 19.68, hole 7.87, Top Layer to Bottom Layer, 16 vias
v3: diameter 23, hole 10, Top Layer to Bottom Layer, 4 vias

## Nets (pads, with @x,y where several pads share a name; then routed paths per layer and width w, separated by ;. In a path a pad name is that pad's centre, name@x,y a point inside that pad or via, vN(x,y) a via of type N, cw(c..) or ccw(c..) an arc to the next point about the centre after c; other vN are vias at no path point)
+1.0V: C4_1.1 C4_2.1 C6_1.1 C6_2.1 C7_1.1 C7_2.1 C8_1.1 C8_2.1 C19_1.1 C19_2.1 C20_1.1 C20_2.1 C21_1.1 C21_2.1 C29_1.1 C29_2.1 C30_1.1 C30_2.1 C31_1.1 C31_2.1 C32_1.1 C32_2.1 J101.1 J101.2 J102.3 J102.4 pad.0@1825,1600 pad.0@1825,3100 R4_1.1 R4_2.1 R9_1.2 R9_2.2 U1_1.3 U1_1.5 U1_2.3 U1_2.5 | length 2652.8
  Top Layer w9: v1(475,825) R4_1.1@533.5,825 ; v1(475,3125) R4_2.1@533.5,3125
  Mid-Layer 3 w9: J101.2@200,1700 300,1700 325,1675 325,1075 500,900 500,850 v1(475,825) ; J102.3@200,2300 325,2300 350,2325 350,3000 v1(475,3125)
  Bottom Layer w9: R9_1.2@241.5,275 241.5,291.5 v1(275,325) 283.5,316.5 C4_1.1@283.5,275 ; R9_2.2@241.5,3775 241.5,3791.5 v1(275,3825) 283.5,3816.5 C4_2.1@283.5,3775
  Bottom Layer w15: v1(1725,1625) 1800,1625 pad.0@1825,1600 ; v1(1725,3125) 1800,3125 pad.0@1825,3100
  other v1: 1725,725 1875,725 2025,725 1725,775 1875,775 2025,775 1725,825 1725,875 1725,925 1725,975 1725,1025 1725,1075 1725,1125 1725,1175 1725,1425 1725,1475 1725,1525 1725,1575 125,1625 275,1625 125,1675 275,1675 1725,1675 125,1725 275,1725 525,1725 575,1725 625,1725 675,1725 825,1725 875,1725 925,1725 975,1725 1725,1725 125,1775 275,1775 1725,1775 125,1825 275,1825 1725,1825 1875,1825 2025,1825 125,1875 275,1875 1725,1875 1875,1875 2025,1875 125,1925 275,1925 127.74,2018.76 275,2025 125,2075 275,2075 277.74,2118.76 125,2125 125,2175 275,2175 125,2225 275,2225 1725,2225 1875,2225 2025,2225 125,2275 275,2275 525,2275 575,2275 625,2275 675,2275 825,2275 875,2275 925,2275 975,2275 1725,2275 1875,2275 2025,2275 125,2325 275,2325 1725,2325 125,2375 275,2375 1725,2375 1725,2425 1725,2475 1725,2525 1725,2575 1725,2625 1725,2675 1725,2925 1725,2975 1725,3025 1725,3075 1725,3175 1725,3225 1725,3275 1725,3325 1875,3325 2025,3325 1725,3375 1875,3375 2025,3375
+2.5V: J107.1 R103.2 R104.2 | length 441.9
  Bottom Layer w9: J107.1@2000,300 2000,519.45 2054.18,573.62 R104.2@2100,573.62 R103.2@2200,573.62
+3.3V: J106.5
+7V: C13_1.1 C13_2.1 J103.1 U1_1.4 U1_2.4 | length 3458.6
  Top Layer w15: v1(1725,1225) 1799,1299 U1_1.4@1799,1300 ; v1(1725,2725) 1799,2799 U1_2.4@1799,2800
  Mid-Layer 2 w40: v1(1025,1225) v1(1725,1225) ; v1(1025,2775) 1600,2775 1650,2725 v1(1725,2725)
  Mid-Layer 3 w40: J103.1@1025,1100 v1(1025,1225) v1(1025,2775)
  Bottom Layer w15: v1(1725,1225) 1739,1239 C13_1.1@1795,1239 ; v1(1725,2725) 1739,2739 C13_2.1@1795,2739
AVSCLK: J107.3 R103.1 U2_1.10 | length 2427.3
  Mid-Layer 2 w9: v1(1475,675) 1600,550 1950,550 J107.3@2200,300 ; v1(1475,1475) 1500,1500 1800,1500 1825,1475 v1(1875,1475)
  Mid-Layer 3 w9: v1(1475,675) 1450,700 1450,1450 v1(1475,1475)
  Bottom Layer w9: v1(1875,1475) 1911.44,1438.56 U2_1.10@1932,1438.56 ; J107.3@2200,300 R103.1@2200,533.5
AVSCLK_NC: U2_2.10 | length 72.1
  Bottom Layer w9: v1(1875,2975) 1911.44,2938.56 U2_2.10@1932,2938.56
AVSDATA: J107.2 R104.1 U2_1.9 | length 2330.9
  Mid-Layer 2 w9: v1(1475,625) 1575,525 1950,525 2100,375 J107.2@2100,300 ; v1(1475,1425) 1500,1450 1800,1450 1825,1425 v1(1875,1425)
  Mid-Layer 3 w9: v1(1475,625) 1500,650 1500,1400 v1(1475,1425)
  Bottom Layer w9: v1(1875,1425) 1881.12,1418.88 U2_1.9@1932,1418.88 ; J107.2@2100,300 R104.1@2100,526.38
AVSDATA_NC: U2_2.9 | length 59.5
  Bottom Layer w9: v1(1875,2925) 1881.12,2918.88 U2_2.9@1932,2918.88
CLK: J106.9 U2_1.7 U2_2.7 | length 3185.9
  Mid-Layer 3 w9: J106.9@1500,300 1575,300 1625,350 1625,1275 v1(1725,1375) 1700,1375 1675,1400 1675,2825 v1(1725,2875)
  Bottom Layer w9: v1(1725,1375) 1902.5,1375 1907.02,1379.52 U2_1.7@1932,1379.52 ; v1(1725,2875) 1902.5,2875 1907.02,2879.52 U2_2.7@1932,2879.52
COMP: C2_1.1 C2_2.1 C3_1.1 C3_2.1 U2_1.15 U2_1.36 U2_2.15 U2_2.36 | length 2942.3
  Mid-Layer 2 w7: v1(1925,1575) 1925,1225 1950,1200 1950,1100 v1(1975,1075) ; v1(1925,3075) 1925,2725 1950,2700 1950,2600 v1(1975,2575)
  Mid-Layer 3 w9: v1(1925,1575) 1975,1625 v1(1975,2575)
  Bottom Layer w9: v1(1925,1575) 1950,1550 1975,1550 2040.16,1484.84 U2_1.15@2040.16,1468 ; v1(1925,3075) 1950,3050 1975,3050 2040.16,2984.84 U2_2.15@2040.16,2968 ; C3_1.1@2000,1001.5 2003.5,1005 C2_1.1@2003.5,1040 1975,1068.5 v1(1975,1075) 1975,1085 2025,1135 2025,1175 2040.16,1190.16 U2_1.36@2040.16,1232 ; C3_2.1@2000,2501.5 2003.5,2505 C2_2.1@2003.5,2540 1975,2568.5 v1(1975,2575) 1975,2585 2025,2635 2025,2675 2040.16,2690.16 U2_2.36@2040.16,2732
DATA: J106.10 U2_1.6 U2_2.6 | length 3413
  Mid-Layer 3 w9: J106.10@1500,400 1450,350 1450,275 1475,250 1550,250 1650,350 1650,1250 v1(1725,1325) 1750,1350 1750,1390 1740,1400 1710,1400 1700,1410 1700,2813 1712,2825 v1(1725,2825)
  Bottom Layer w9: v1(1725,1325) 1800,1325 1834.84,1359.84 U2_1.6@1932,1359.84 ; v1(1725,2825) 1800,2825 1834.84,2859.84 U2_2.6@1932,2859.84
EN1: J104.1 J106.7 U2_1.3 U2_2.3 | length 3728.8
  Mid-Layer 2 w9: J104.1@1025,775 1350.2,449.8 1350.2,330 J106.7@1390.1,290.1 ; J106.7@1400,300 1450,350 1450,750 1700,1000 1750,1000 1800,1050 1800,1200 v1(1875,1275)
  Mid-Layer 3 w9: v1(1875,1275) 1900,1250 1900,1210 1890,1200 1850,1200 1800,1250 1800,2700 v1(1875,2775)
  Bottom Layer w9: v1(1875,1275) 1900.8,1300.8 U2_1.3@1932,1300.8 ; v1(1875,2775) 1900.8,2800.8 U2_2.3@1932,2800.8
FLT: R12_1.1 R12_2.1 U2_1.17 U2_1.34 U2_2.17 U2_2.34 | length 3019.1
  Mid-Layer 2 w7: v1(2025,1575) 2000,1600 1962.5,1600 1950,1587.5 1950,1250 2000,1200 2000,1150 v1(2075,1075) ; v1(2025,3075) 2000,3100 1962.5,3100 1950,3087.5 1950,2750 2000,2700 2000,2650 v1(2075,2575)
  Mid-Layer 3 w9: v1(2025,1575) 2050,1600 2050,2550 v1(2075,2575)
  Bottom Layer w9: v1(2025,1575) 2079.52,1520.48 U2_1.17@2079.52,1468 ; v1(2025,3075) 2079.52,3020.48 U2_2.17@2079.52,2968 ; U2_1.34@2079.52,1232 2079.52,1179.52 2070,1170 2070,1110 2075,1105 v1(2075,1075) 2075,1063.5 R12_1.1@2103.5,1035 ; U2_2.34@2079.52,2732 2079.52,2679.52 2070,2670 2070,2610 2075,2605 v1(2075,2575) 2075,2563.5 R12_2.1@2103.5,2535
GND: C4_1.2 C4_2.2 C5_1.1 C5_2.1 C6_1.2 C6_2.2 C7_1.2 C7_2.2 C8_1.2 C8_2.2 C9_1.2 C9_2.2 C10_1.2 C10_2.2 C11_1.2 C11_2.2 C12_1.2 C12_2.2 C13_1.2 C13_2.2 C14_1.2 C14_2.2 C16_1.2 C16_2.2 C17_1.2 C17_2.2 C19_1.2 C19_2.2 C20_1.2 C20_2.2 C21_1.2 C21_2.2 C22_1.2 C22_2.2 C23_1.2 C23_2.2 C24_1.2 C24_2.2 C25_1.2 C25_2.2 C26_1.2 C26_2.2 C27_1.2 C27_2.2 C28_1.2 C28_2.2 C29_1.2 C29_2.2 C30_1.2 C30_2.2 C31_1.2 C31_2.2 C32_1.2 C32_2.2 C100.2 J1_1.2 J1_1.3 J1_2.2 J1_2.3 J100.1 J100.2 J101.3 J101.4 J102.1 J102.2 J103.2 J104.2 J105.2 J106.6 J107.4 R5_1.1 R5_2.1 R7_1.1 R7_2.1 R8_1.1 R8_2.1 R11_1.1 R11_2.1 R15_1.1 R15_2.1 R16_1.1 R16_2.1 U1_1.2 U1_1.6 U1_1.11 U1_2.2 U1_2.6 U1_2.11 U2_1.8 U2_1.13 U2_1.14 U2_1.27 U2_1.41 U2_2.8 U2_2.13 U2_2.14 U2_2.27 U2_2.41 | length 6890.9
  Top Layer w9: v1(475,875) R5_1.1@533.5,875
  Top Layer w15: v1(475,3175) R5_2.1@533.5,3175
  Top Layer w25: v1(2475,1175) 2475,1101 2500,1076 2525,1101 v1(2525,1175) ; v1(2475,1425) 2475,1499 2500,1524 2525,1499 v1(2525,1425) ; v1(2475,2675) 2475,2601 2500,2576 2525,2601 v1(2525,2675) ; v1(2475,2925) 2475,2999 2500,3024 2525,2999 v1(2525,2925)
  Mid-Layer 3 w9: J101.3@200,1500 285,1500 300,1485 300,1050 v1(475,875) ; J102.2@200,2500 300,2500 325,2525 325,3025 v1(475,3175)
  Mid-Layer 3 w25: v3(1925,925) 1885,965 1885,1145 1925,1185 1925,1295.87 v2(1979.13,1350) 1980,1350.87 1980,1470 1890,1560 1890,1640 v3(1925,1675) ; v3(1925,2425) 1885,2465 1885,2645 1925,2685 1925,2795.87 v2(1979.13,2850) 1980,2850.87 1980,2970 1890,3060 1890,3140 v3(1925,3175)
  Bottom Layer w9: v3(1925,925) R7_1.1@1925,953.5 R8_1.1@1960,953.5 1988.5,925 C5_1.1@1998.5,925 ; v3(1925,1675) 1930,1670 C24_1.2@1958.5,1670 ; v3(1925,2425) R8_2.1@1925,2453.5 R7_2.1@1960,2453.5 1988.5,2425 C5_2.1@1998.5,2425 ; v3(1925,3175) 1930,3170 C24_2.2@1958.5,3170
  Bottom Layer w12: U2_1.8@1932,1399.2 U2_1.41@1980.8,1399.2 ; U2_2.8@1932,2899.2 U2_2.41@1980.8,2899.2 ; U2_1.41@2000.8,1424.2 U2_1.13@2000.8,1468 ; U2_2.41@2000.8,2924.2 U2_2.13@2000.8,2968 ; U2_1.41@2020.48,1424.52 U2_1.14@2020.48,1468 ; U2_2.41@2020.48,2924.52 U2_2.14@2020.48,2968 ; U2_1.41@2129.52,1320.48 U2_1.27@2168,1320.48 ; U2_2.41@2129.52,2820.48 U2_2.27@2168,2820.48
  Bottom Layer w15: 1773.5,866.5 C22_1.2@1773.5,915 ; 1773.5,2366.5 C22_2.2@1773.5,2415 ; R15_1.1@1781.25,1455.25 1781.25,1496 1826,1496 1855,1525 v1(1875,1525) ; R15_2.1@1781.25,2955.25 1781.25,2996 1826,2996 1855,3025 v1(1875,3025) ; C23_1.2@1793.5,1660 1793.5,1703.5 ; C23_2.2@1793.5,3160 1793.5,3203.5 ; R11_1.1@1795,1131.5 1795,1181 1819,1181 1825,1175 v1(1875,1175) ; R11_2.1@1795,2631.5 1795,2681 1819,2681 1825,2675 v1(1875,2675) ; v1(2275,1325) 2277.25,1322.75 C16_1.2@2331.25,1322.75 ; v1(2275,2825) 2277.25,2822.75 C16_2.2@2331.25,2822.75 ; v1(2325,1125) 2325,1152.25 C14_1.2@2331.25,1158.5 ; v1(2325,1475) 2325,1435.25 C17_1.2@2331.25,1429 ; v1(2325,2625) 2325,2652.25 C14_2.2@2331.25,2658.5 ; v1(2325,2975) 2325,2935.25 C17_2.2@2331.25,2929
  Bottom Layer w25: v1(2475,1175) 2475,1101 2500,1076 2525,1101 v1(2525,1175) ; v1(2475,1425) 2475,1499 2500,1524 2525,1499 v1(2525,1425) ; v1(2475,2675) 2475,2601 2500,2576 2525,2601 v1(2525,2675) ; v1(2475,2925) 2475,2999 2500,3024 2525,2999 v1(2525,2925)
  other v1: 175,125 275,125 325,325 2175,725 2225,725 2175,775 1875,825 2175,825 1875,875 1920,875 2080,875 2125,875 125,1225 175,1225 225,1225 275,1225 125,1275 275,1275 525,1275 575,1275 625,1275 675,1275 825,1275 875,1275 925,1275 975,1275 125,1325 275,1325 125,1375 275,1375 125,1425 275,1425 125,1475 275,1475 125,1525 275,1525 2325,1525 3725,1625 3775,1625 3825,1625 3875,1625 2125,1675 3725,1675 3875,1675 1875,1725 3725,1725 3875,1725 3225,1750 3275,1750 3325,1750 3375,1750 1875,1775 2175,1775 3725,1775 3875,1775 3225,1800 3375,1800 2175,1825 3725,1825 3875,1825 2175,1875 2225,1875 3725,1875 3875,1875 3725,1925 3875,1925 2175,2225 2225,2225 2175,2275 1875,2325 2175,2325 1875,2375 1920,2375 2080,2375 2125,2375 128.92,2473.8 275,2475 125,2525 275,2525 125,2575 275,2575 125,2625 275,2625 125,2675 275,2675 125,2725 275,2725 525,2725 575,2725 625,2725 675,2725 825,2725 875,2725 925,2725 975,2725 125,2775 175,2775 225,2775 275,2775 2325,3025 2125,3175 1875,3225 1875,3275 2175,3275 2175,3325 2175,3375 2225,3375 175,3625 275,3625 325,3825
  other v2: 2050,1279.13 2050,1318.5 2018.5,1350 2081.5,1350 2120.87,1350 2050,1381.5 2050,1420.87 2050,2779.13 2050,2818.5 2018.5,2850 2081.5,2850 2120.87,2850 2050,2881.5 2050,2920.87
IBV: C9_1.1 C9_2.1 C10_1.1 C10_2.1 C11_1.1 C11_2.1 C12_1.1 C12_2.1 C17_1.1 C17_2.1 C25_1.1 C25_2.1 C26_1.1 C26_2.1 C27_1.1 C27_2.1 C28_1.1 C28_2.1 C100.1 J100.3 J100.4 U1_1.9 U1_1.13 U1_2.9 U1_2.13 U2_1.24 U2_2.24 | length 2083.2
  Top Layer w25: v1(2475,725) 2475,799 2500,824 2525,799 v1(2525,725) ; v1(2475,1875) 2475,1801 2500,1776 2525,1801 v1(2525,1875) ; v1(2475,2225) 2475,2299 2500,2324 2525,2299 v1(2525,2225) ; v1(2475,3375) 2475,3301 2500,3276 2525,3301 v1(2525,3375)
  Bottom Layer w12: U2_1.24@2168,1379.52 2270.48,1379.52 v1(2275,1375) ; U2_2.24@2168,2879.52 2270.48,2879.52 v1(2275,2875)
  Bottom Layer w15: v1(2275,1375) 2279,1371 C17_1.1@2331.25,1371 ; v1(2275,2875) 2279,2871 C17_2.1@2331.25,2871
  Bottom Layer w25: v1(2475,725) 2475,799 2500,824 2525,799 v1(2525,725) ; v1(2475,1875) 2475,1801 2500,1776 2525,1801 v1(2525,1875) ; v1(2475,2225) 2475,2299 2500,2324 2525,2299 v1(2525,2225) ; v1(2475,3375) 2475,3301 2500,3276 2525,3301 v1(2525,3375)
  other v1: 2275,725 2325,725 2275,875 2325,875 2275,1025 2325,1025 2275,1575 2325,1575 2275,1725 2325,1725 2275,1875 2325,1875 3725,2025 3875,2025 3725,2075 3875,2075 3725,2125 3875,2125 3725,2175 3875,2175 3225,2200 3375,2200 2275,2225 2325,2225 3725,2225 3875,2225 3225,2250 3275,2250 3325,2250 3375,2250 3725,2275 3875,2275 3725,2325 3875,2325 2275,2375 2325,2375 3725,2375 3775,2375 3825,2375 3875,2375 2275,2525 2325,2525 2275,3075 2325,3075 2275,3225 2325,3225 2275,3375 2325,3375
ISH: U2_1.21 U2_1.30 U2_2.21 U2_2.30 | length 2683.1
  Mid-Layer 2 w7: v1(2275,1075) 2300,1100 2300,1450 v1(2275,1475) ; v1(2275,2575) 2300,2600 2300,2950 v1(2275,2975)
  Mid-Layer 3 w9: v1(2275,1475) 2250,1500 2250,2550 v1(2275,2575)
  Bottom Layer w9: U2_1.30@2168,1261.44 2181.06,1261.44 2192.5,1250 2192.5,1197.5 2205,1185 2205,1145 v1(2275,1075) ; U2_1.21@2168,1438.56 2186.06,1438.56 2222.5,1475 v1(2275,1475) ; U2_2.30@2168,2761.44 2181.06,2761.44 2192.5,2750 2192.5,2697.5 2205,2685 2205,2645 v1(2275,2575) ; U2_2.21@2168,2938.56 2186.06,2938.56 2222.5,2975 v1(2275,2975)
NetC1_1_1: C1_1.1 pad.0@1870,1045 R1_1.2 | length 90.9
  Bottom Layer w9: pad.0@1870,1045 1885,1060 R1_1.2@1913.5,1060 1913.5,1040 C1_1.1@1928.5,1025
NetC1_1_2: C1_1.2 C3_1.2 R2_1.1 R3_1.1 R6_1.1 R7_1.2 R8_1.2 R10_1.1 U2_1.35 | length 1436
  Mid-Layer 2 w7: v1(1925,1625) 1900,1600 1900,1050 1950,1000 2050,1000 v1(2075,975)
  Bottom Layer w9: R2_1.1@1805,968.5 R3_1.1@1865,968.5 1888.5,968.5 1906.5,986.5 R7_1.2@1925,986.5 R8_1.2@1960,986.5 ; v1(1925,1625) R10_1.1@1968.5,1625 ; C1_1.2@1961.5,1025 1961.5,988 R8_1.2@1960,986.5 ; U2_1.35@2059.84,1232 2059.84,1184.84 2050,1175 2050,1065 2075,1040 v1(2075,975) 2068.5,968.5 R6_1.1@2040,968.5 C3_1.2@2000,968.5 1986.5,968.5 1980,975 1980,980 1973.5,986.5 R8_1.2@1960,986.5
NetC1_2_1: C1_2.1 pad.0@1870,2545 R1_2.2 | length 90.9
  Bottom Layer w9: pad.0@1870,2545 1885,2560 R1_2.2@1913.5,2560 1913.5,2540 C1_2.1@1928.5,2525
NetC1_2_2: C1_2.2 C3_2.2 R2_2.1 R3_2.1 R6_2.1 R7_2.2 R8_2.2 R10_2.1 U2_2.35 | length 1433.5
  Mid-Layer 2 w7: v1(1925,3125) 1900,3100 1900,2550 1950,2500 2050,2500 v1(2075,2475)
  Bottom Layer w9: R2_2.1@1805,2468.5 1888.5,2468.5 1906.5,2486.5 R8_2.2@1925,2486.5 R7_2.2@1960,2486.5 ; v1(1925,3125) R10_2.1@1968.5,3125 ; C1_2.2@1961.5,2525 1960,2523.5 R7_2.2@1960,2486.5 ; U2_2.35@2059.84,2732 2059.84,2684.84 2054,2679 2054,2610 2053,2609 2053,2562 2075,2540 v1(2075,2475) 2068.5,2468.5 R6_2.1@2040,2468.5 C3_2.2@2000,2468.5 1987,2481.5 1960,2481.5 R7_2.2@1960,2486.5
NetC2_1_2: C2_1.2 pad.0@2020,1085 R6_1.2 | length 91.8
  Bottom Layer w9: pad.0@2020,1085 2020,1070 2036.5,1053.5 C2_1.2@2036.5,1040 2036.5,1005 R6_1.2@2040,1001.5
NetC2_2_2: C2_2.2 pad.0@2020,2585 R6_2.2 | length 91.8
  Bottom Layer w9: pad.0@2020,2585 2036.5,2568.5 C2_2.2@2036.5,2540 2036.5,2505 R6_2.2@2040,2501.5
NetC5_1_2: C5_1.2 U1_1.15 U2_1.31 | length 837.3
  Top Layer w9: U1_1.15@2000,849 2000,900 2025,925 v1(2075,925)
  Mid-Layer 2 w7: v1(2075,925) 2100,900 2187.5,900 2300,1012.5 2300,1050 v1(2325,1075)
  Bottom Layer w9: C5_1.2@2031.5,925 v1(2075,925) ; U2_1.31@2138.56,1232 2138.56,1196.44 2185,1150 2185,1130 2262.5,1052.5 2302.5,1052.5 v1(2325,1075)
NetC5_2_2: C5_2.2 U1_2.15 U2_2.31 | length 837.3
  Top Layer w9: U1_2.15@2000,2349 2000,2400 2025,2425 v1(2075,2425)
  Mid-Layer 2 w7: v1(2075,2425) 2100,2400 2187.5,2400 2300,2512.5 2300,2550 v1(2325,2575)
  Bottom Layer w9: C5_2.2@2031.5,2425 v1(2075,2425) ; U2_2.31@2138.56,2732 2138.56,2696.44 2185,2650 2185,2630 2262.5,2552.5 2302.5,2552.5 v1(2325,2575)
NetC14_1_1: C14_1.1 R12_1.2 U2_1.26 | length 606
  Mid-Layer 2 w7: v1(2125,975) 2225,1075 2225,1175 v1(2275,1225)
  Bottom Layer w7: v1(2275,1225) 2283.5,1216.5 C14_1.1@2331.25,1216.5
  Bottom Layer w9: v1(2125,975) 2136.5,986.5 R12_1.2@2136.5,1035 ; U2_1.26@2168,1340.16 2184.84,1340.16 2245,1280 2245,1255 v1(2275,1225)
NetC14_2_1: C14_2.1 R12_2.2 U2_2.26 | length 606
  Mid-Layer 2 w7: v1(2125,2475) 2225,2575 2225,2675 v1(2275,2725)
  Bottom Layer w9: v1(2125,2475) 2136.5,2486.5 R12_2.2@2136.5,2535 ; U2_2.26@2168,2840.16 2184.84,2840.16 2245,2780 2245,2755 v1(2275,2725) 2283.5,2716.5 C14_2.1@2331.25,2716.5
NetC15_1_1: C15_1.1 pad.0@2150,1125 R13_1.1 U2_1.32 | length 226.7
  Bottom Layer w9: U2_1.32@2118.88,1232 2118.88,1181.12 2150,1150 pad.0@2150,1125 2136.5,1111.5 C15_1.1@2136.5,1075 2155,1075 2161.5,1081.5 R13_1.1@2185,1081.5
NetC15_1_2: C15_1.2 C22_1.1 U1_1.1 U2_1.33 | length 720.6
  Top Layer w10: U1_1.1@1799,904 1854,904 v1(1875,925)
  Mid-Layer 2 w10: v1(1875,925) 1900,950 2090,950 2100,960 v1(2100,1125)
  Bottom Layer w10: C22_1.1@1806.5,915 1865,915 v1(1875,925) ; U2_1.33@2099.2,1232 2099.2,1125.8 v1(2100,1125) 2103.5,1121.5 C15_1.2@2103.5,1075
NetC15_2_1: C15_2.1 pad.0@2150,2625 R13_2.1 U2_2.32 | length 219.6
  Bottom Layer w9: U2_2.32@2118.88,2732 2118.88,2681.12 2150,2650 pad.0@2150,2625 2141.5,2616.5 C15_2.1@2141.5,2575 2155,2575 2161.5,2581.5 R13_2.1@2185,2581.5
NetC15_2_2: C15_2.2 C22_2.1 U1_2.1 U2_2.33 | length 722.7
  Top Layer w9: U1_2.1@1799,2404 1854,2404 v1(1875,2425)
  Mid-Layer 2 w10: v1(1875,2425) 1900,2450 2090,2450 2100,2460 v1(2100,2625)
  Bottom Layer w9: C22_2.1@1806.5,2415 1865,2415 v1(1875,2425) ; U2_2.33@2099.2,2732 2099.2,2625.8 v1(2100,2625) 2108.5,2616.5 C15_2.2@2108.5,2575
